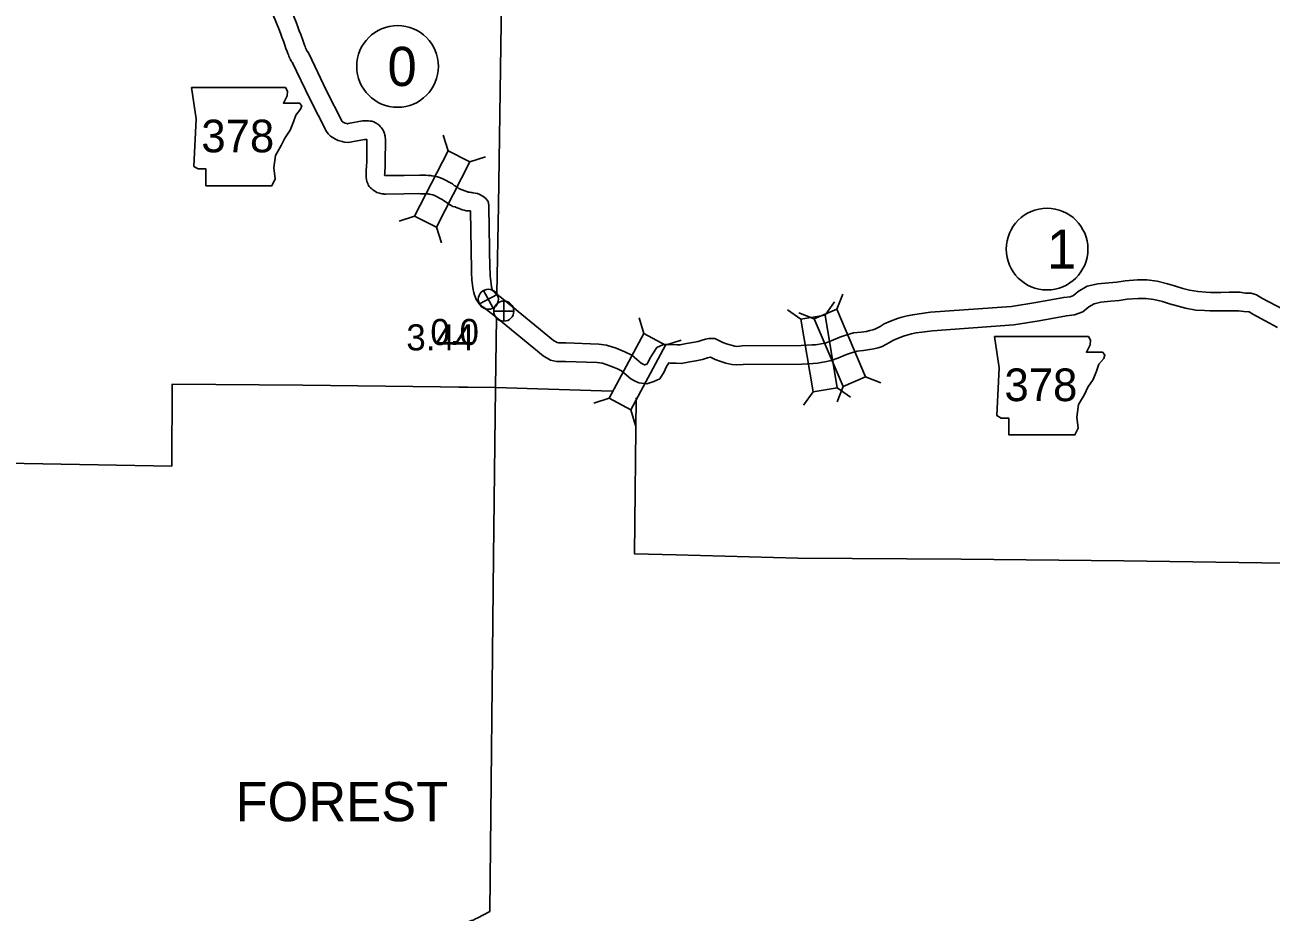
# Model space of a CAD drawing. Extents: x -939622 to -934245, y 1383184 to 1385301.
# Drawn here: x -936377.4 to -936316.9, y 1384357.3 to 1384400.3 of the extents above; entities that cross this region are included whole.
import ezdxf

# ---------------------------------------------------------------- set-up
doc = ezdxf.new("R2010")
doc.units = 0
for name, color, linetype in [('Level 10', 7, 'Continuous'), ('Level 2', 7, 'Continuous'), ('Level 20', 7, 'Continuous'), ('Level 21', 7, 'Continuous'), ('Level 25', 7, 'Continuous'), ('Level 26', 7, 'Continuous'), ('Level 27', 7, 'Continuous'), ('Level 8', 7, 'Continuous')]:
    doc.layers.add(name, color=color, linetype=linetype)

msp = doc.modelspace()

# ---------------------------------------------------------------- linework, layer by layer
at = {"layer": 'Level 10'}
msp.add_line((-936355.168, 1384391.993), (-936355.035, 1384391.879), dxfattribs=at)
for points in [[(-936365.019, 1384402.168), (-936364.906, 1384401.963), (-936364.844, 1384401.842), (-936364.785, 1384401.715), (-936364.684, 1384401.489), (-936364.576, 1384401.252), (-936364.486, 1384401.057), (-936364.413, 1384400.891), (-936364.343, 1384400.709), (-936364.234, 1384400.432), (-936364.146, 1384400.206), (-936364.076, 1384400.007), (-936364.006, 1384399.825), (-936363.927, 1384399.604), (-936363.877, 1384399.456), (-936363.819, 1384399.307), (-936363.799, 1384399.248), (-936363.773, 1384399.191), (-936363.748, 1384399.126), (-936363.728, 1384399.082), (-936363.706, 1384399.033)], [(-936365.806, 1384401.733), (-936365.701, 1384401.542), (-936365.653, 1384401.448), (-936365.603, 1384401.341), (-936365.504, 1384401.119), (-936365.394, 1384400.877), (-936365.307, 1384400.688), (-936365.246, 1384400.549), (-936365.182, 1384400.383), (-936365.072, 1384400.104), (-936364.99, 1384399.892), (-936364.92, 1384399.696), (-936364.85, 1384399.512), (-936364.777, 1384399.308), (-936364.723, 1384399.15), (-936364.665, 1384399), (-936364.636, 1384398.914), (-936364.602, 1384398.84), (-936364.578, 1384398.779), (-936364.549, 1384398.715), (-936364.529, 1384398.668)], [(-936363.716, 1384399.054), (-936363.701, 1384399.024), (-936363.681, 1384398.999), (-936363.617, 1384398.904)], [(-936363.617, 1384398.904), (-936362.759, 1384397.105), (-936362.001, 1384395.604), (-936361.982, 1384395.593), (-936361.91, 1384395.558), (-936361.86, 1384395.531), (-936361.832, 1384395.523), (-936361.776, 1384395.51), (-936361.754, 1384395.504), (-936361.735, 1384395.502), (-936361.709, 1384395.508), (-936361.015, 1384395.638), (-936360.907, 1384395.642), (-936360.845, 1384395.647), (-936360.719, 1384395.643), (-936360.644, 1384395.632), (-936360.558, 1384395.622), (-936360.459, 1384395.59), (-936360.374, 1384395.549), (-936360.319, 1384395.512), (-936360.286, 1384395.487), (-936360.274, 1384395.479), (-936360.187, 1384395.419), (-936360.131, 1384395.345), (-936360.108, 1384395.318), (-936360.092, 1384395.299), (-936360.064, 1384395.262), (-936360.007, 1384395.184), (-936359.98, 1384395.112), (-936359.944, 1384395.035), (-936359.929, 1384394.95), (-936359.918, 1384394.903), (-936359.907, 1384394.831), (-936359.901, 1384394.76), (-936359.9, 1384394.688), (-936359.909, 1384393.675), (-936359.905, 1384393.599), (-936359.911, 1384393.476), (-936359.934, 1384393.111), (-936359.937, 1384393.003), (-936359.928, 1384393), (-936359.89, 1384392.989), (-936359.89, 1384392.989), (-936359.869, 1384392.987), (-936358.992, 1384393)], [(-936364.519, 1384398.647), (-936364.467, 1384398.545), (-936364.414, 1384398.476), (-936364.383, 1384398.429)], [(-936364.416, 1384398.486), (-936363.567, 1384396.709), (-936362.765, 1384395.119), (-936362.685, 1384395.009), (-936362.566, 1384394.892), (-936362.407, 1384394.799), (-936362.322, 1384394.758), (-936362.198, 1384394.69), (-936362.058, 1384394.652), (-936361.994, 1384394.636), (-936361.945, 1384394.624), (-936361.871, 1384394.607), (-936361.697, 1384394.591), (-936361.534, 1384394.625), (-936360.912, 1384394.741), (-936360.852, 1384394.744), (-936360.824, 1384394.746), (-936360.805, 1384394.745), (-936360.803, 1384394.737), (-936360.801, 1384394.725), (-936360.801, 1384394.717), (-936360.8, 1384394.688), (-936360.809, 1384393.654), (-936360.806, 1384393.598), (-936360.81, 1384393.528), (-936360.834, 1384393.149), (-936360.839, 1384392.901), (-936360.824, 1384392.805), (-936360.808, 1384392.697), (-936360.761, 1384392.597), (-936360.735, 1384392.544), (-936360.686, 1384392.465), (-936360.618, 1384392.389), (-936360.567, 1384392.345), (-936360.506, 1384392.295), (-936360.428, 1384392.245), (-936360.309, 1384392.172), (-936360.182, 1384392.137), (-936360.124, 1384392.119), (-936360.063, 1384392.102), (-936359.999, 1384392.095), (-936359.956, 1384392.091), (-936359.888, 1384392.087), (-936359.003, 1384392.1)], [(-936358.992, 1384393), (-936358.223, 1384393.012), (-936358.172, 1384393.004), (-936358.149, 1384393.006), (-936358.036, 1384393.007), (-936358.009, 1384393.004), (-936357.935, 1384393.012), (-936357.851, 1384392.998), (-936357.821, 1384392.996), (-936357.751, 1384392.993), (-936357.699, 1384392.987), (-936357.643, 1384392.984), (-936357.54, 1384392.965), (-936357.472, 1384392.943), (-936357.44, 1384392.938), (-936357.367, 1384392.922), (-936357.322, 1384392.914), (-936357.231, 1384392.887), (-936357.117, 1384392.829), (-936356.645, 1384392.587), (-936356.56, 1384392.514), (-936356.391, 1384392.402), (-936356.344, 1384392.369), (-936356.338, 1384392.365), (-936356.309, 1384392.353), (-936356.183, 1384392.304)], [(-936356.183, 1384392.304), (-936355.921, 1384392.202), (-936355.909, 1384392.197), (-936355.864, 1384392.187), (-936355.824, 1384392.176), (-936355.763, 1384392.172), (-936355.702, 1384392.16), (-936355.655, 1384392.156), (-936355.436, 1384392.127), (-936355.314, 1384392.063), (-936355.304, 1384392.057), (-936355.272, 1384392.046), (-936355.2, 1384392.01), (-936355.168, 1384391.993)], [(-936359.003, 1384392.1), (-936358.287, 1384392.111), (-936358.193, 1384392.096), (-936358.096, 1384392.107), (-936358.084, 1384392.107), (-936358.014, 1384392.099), (-936357.978, 1384392.102), (-936357.861, 1384392.097), (-936357.823, 1384392.096), (-936357.779, 1384392.09), (-936357.755, 1384392.089), (-936357.682, 1384392.065), (-936357.606, 1384392.053), (-936357.554, 1384392.042), (-936357.527, 1384392.028), (-936357.149, 1384391.834), (-936357.102, 1384391.794), (-936356.897, 1384391.657), (-936356.841, 1384391.619), (-936356.763, 1384391.57), (-936356.736, 1384391.558), (-936356.632, 1384391.487), (-936356.535, 1384391.475), (-936356.509, 1384391.465)], [(-936355.035, 1384391.879), (-936354.918, 1384391.731), (-936354.886, 1384391.552), (-936354.886, 1384391.529), (-936354.877, 1384391.473), (-936354.834, 1384388.445), (-936354.826, 1384388.317), (-936354.826, 1384388.231), (-936354.817, 1384388.109), (-936354.808, 1384388.015), (-936354.756, 1384387.595), (-936354.751, 1384387.574), (-936354.739, 1384387.54), (-936354.719, 1384387.463), (-936354.716, 1384387.451), (-936354.708, 1384387.433), (-936354.651, 1384387.358), (-936354.618, 1384387.326), (-936354.591, 1384387.306), (-936354.499, 1384387.235)], [(-936356.499, 1384391.461), (-936356.248, 1384391.363), (-936356.17, 1384391.333), (-936356.082, 1384391.314), (-936355.978, 1384391.285), (-936355.774, 1384391.271)], [(-936355.774, 1384391.271), (-936355.733, 1384388.413), (-936355.726, 1384388.288), (-936355.725, 1384388.194), (-936355.714, 1384388.034), (-936355.703, 1384387.918), (-936355.644, 1384387.444), (-936355.618, 1384387.322), (-936355.599, 1384387.272), (-936355.588, 1384387.23), (-936355.567, 1384387.152), (-936355.531, 1384387.068), (-936355.496, 1384386.985), (-936355.449, 1384386.911), (-936355.353, 1384386.765), (-936355.237, 1384386.672), (-936355.203, 1384386.639), (-936355.133, 1384386.588), (-936354.526, 1384386.119)], [(-936354.181, 1384386.989), (-936351.747, 1384384.988), (-936351.57, 1384384.89), (-936351.507, 1384384.876), (-936351.142, 1384384.874), (-936349.55, 1384384.818), (-936349.169, 1384384.764), (-936348.711, 1384384.612), (-936348.476, 1384384.517), (-936348.293, 1384384.447), (-936347.954, 1384384.283), (-936347.727, 1384384.085), (-936347.491, 1384383.887), (-936347.364, 1384383.819), (-936347.336, 1384383.804), (-936347.312, 1384383.801), (-936347.219, 1384383.833), (-936347.213, 1384383.835), (-936347.17, 1384383.902), (-936347.072, 1384384.11), (-936346.916, 1384384.379), (-936346.731, 1384384.648), (-936346.412, 1384384.792), (-936346.17, 1384384.799), (-936346.062, 1384384.796), (-936345.746, 1384384.781), (-936345.615, 1384384.774), (-936345.298, 1384384.836), (-936345.007, 1384384.886), (-936344.733, 1384384.944), (-936344.529, 1384385.003), (-936344.369, 1384385.052), (-936344.21, 1384385.084), (-936343.919, 1384385.086), (-936343.541, 1384384.892), (-936343.353, 1384384.824), (-936343.136, 1384384.757), (-936342.954, 1384384.71), (-936342.854, 1384384.704), (-936342.59, 1384384.723), (-936339.73, 1384384.743), (-936339.208, 1384384.777), (-936339.036, 1384384.786), (-936338.675, 1384384.847), (-936338.53, 1384384.879), (-936338.28, 1384384.967), (-936337.863, 1384385.146), (-936337.563, 1384385.247), (-936337.202, 1384385.354), (-936336.826, 1384385.394), (-936336.572, 1384385.432), (-936336.401, 1384385.466), (-936336.257, 1384385.5), (-936336.167, 1384385.531), (-936335.907, 1384385.667), (-936335.713, 1384385.795), (-936335.394, 1384385.923), (-936335.067, 1384386.05), (-936334.856, 1384386.115), (-936334.592, 1384386.186), (-936334.322, 1384386.242), (-936334.015, 1384386.289), (-936333.461, 1384386.359), (-936329.53, 1384386.643), (-936328.351, 1384386.836), (-936326.998, 1384387.082), (-936326.687, 1384387.114), (-936326.521, 1384387.176), (-936326.293, 1384387.361), (-936325.856, 1384387.617), (-936325.344, 1384387.736), (-936324.807, 1384387.785), (-936324.421, 1384387.826), (-936324.025, 1384387.889), (-936323.418, 1384387.926), (-936322.968, 1384387.927), (-936322.475, 1384387.864), (-936321.972, 1384387.745), (-936321.619, 1384387.637), (-936321.215, 1384387.519), (-936320.893, 1384387.433), (-936320.486, 1384387.36), (-936320.115, 1384387.336), (-936319.884, 1384387.321), (-936319.379, 1384387.325), (-936318.97, 1384387.329), (-936318.455, 1384387.331), (-936318.187, 1384387.287), (-936317.904, 1384387.279), (-936317.647, 1384387.207), (-936317.385, 1384387.048), (-936316.346, 1384386.492)], [(-936354.517, 1384386.1), (-936352.255, 1384384.241), (-936351.89, 1384384.038), (-936351.605, 1384383.977), (-936351.161, 1384383.974), (-936349.63, 1384383.92), (-936349.375, 1384383.884), (-936349.021, 1384383.767), (-936348.805, 1384383.68), (-936348.651, 1384383.621), (-936348.455, 1384383.525), (-936348.313, 1384383.402), (-936347.999, 1384383.137), (-936347.783, 1384383.022), (-936347.606, 1384382.93), (-936347.217, 1384382.883), (-936346.874, 1384382.999), (-936346.593, 1384383.137), (-936346.382, 1384383.463), (-936346.275, 1384383.69), (-936346.154, 1384383.898), (-936346.154, 1384383.898), (-936346.095, 1384383.897), (-936345.793, 1384383.882), (-936345.552, 1384383.869), (-936345.134, 1384383.951), (-936344.838, 1384384.002), (-936344.515, 1384384.07), (-936344.271, 1384384.141), (-936344.149, 1384384.178), (-936344.129, 1384384.182), (-936343.902, 1384384.066), (-936343.639, 1384383.97), (-936343.382, 1384383.891), (-936343.095, 1384383.817), (-936342.848, 1384383.802), (-936342.554, 1384383.823), (-936339.698, 1384383.843), (-936339.154, 1384383.879), (-936338.937, 1384383.891), (-936338.503, 1384383.963), (-936338.282, 1384384.012), (-936337.953, 1384384.128), (-936337.541, 1384384.305), (-936337.291, 1384384.389), (-936337.025, 1384384.468), (-936336.712, 1384384.501), (-936336.416, 1384384.545), (-936336.21, 1384384.587), (-936336.007, 1384384.634), (-936335.811, 1384384.702), (-936335.45, 1384384.89), (-936335.293, 1384384.993), (-936335.064, 1384385.086), (-936334.77, 1384385.199), (-936334.604, 1384385.251), (-936334.384, 1384385.31), (-936334.163, 1384385.356), (-936333.89, 1384385.398), (-936333.372, 1384385.463), (-936329.424, 1384385.749), (-936328.198, 1384385.95), (-936326.871, 1384386.19), (-936326.481, 1384386.231), (-936326.069, 1384386.384), (-936325.779, 1384386.619), (-936325.519, 1384386.771), (-936325.2, 1384386.846), (-936324.719, 1384386.89), (-936324.303, 1384386.934), (-936323.927, 1384386.993), (-936323.39, 1384387.026), (-936323.025, 1384387.027), (-936322.636, 1384386.977), (-936322.208, 1384386.876), (-936321.876, 1384386.774), (-936321.457, 1384386.653), (-936321.089, 1384386.553), (-936320.595, 1384386.466), (-936320.174, 1384386.438), (-936319.908, 1384386.421), (-936319.371, 1384386.426), (-936318.965, 1384386.429), (-936318.527, 1384386.43), (-936318.272, 1384386.389), (-936318.04, 1384386.383), (-936318.009, 1384386.374), (-936317.831, 1384386.266), (-936316.63, 1384385.623)], [(-936354.488, 1384387.227), (-936354.192, 1384386.997)]]:
    msp.add_lwpolyline(points, dxfattribs=at)
at = {"layer": 'Level 2'}
for points in [[(-936354.499, 1384387.27), (-936354.41, 1384391.534), (-936354.205, 1384405.921), (-936357.731, 1384405.958), (-936357.73, 1384406.03)], [(-936354.499, 1384387.266), (-936354.41, 1384391.534), (-936354.205, 1384405.921), (-936357.731, 1384405.958), (-936357.73, 1384406.03)], [(-936354.653, 1384374.501), (-936354.565, 1384382.691), (-936354.518, 1384386.112)], [(-936354.653, 1384374.501), (-936354.565, 1384382.691), (-936354.519, 1384386.084)], [(-936356.348, 1384356.69), (-936356.268, 1384356.71), (-936356.19, 1384356.718), (-936356.125, 1384356.737), (-936356.023, 1384356.748), (-936355.943, 1384356.771), (-936355.836, 1384356.812), (-936355.72, 1384356.85), (-936355.646, 1384356.873), (-936355.527, 1384356.939), (-936355.423, 1384356.98), (-936354.837, 1384357.286), (-936354.653, 1384374.501)], [(-936356.348, 1384356.69), (-936356.268, 1384356.71), (-936356.19, 1384356.718), (-936356.125, 1384356.737), (-936356.023, 1384356.748), (-936355.943, 1384356.771), (-936355.836, 1384356.812), (-936355.72, 1384356.85), (-936355.646, 1384356.873), (-936355.527, 1384356.939), (-936355.423, 1384356.98), (-936354.837, 1384357.286), (-936354.653, 1384374.501)]]:
    msp.add_lwpolyline(points, dxfattribs=at)
at = {"layer": 'Level 20'}
for p, q in [((-936356.856, 1384394.193), (-936357.098, 1384394.947)), ((-936355.799, 1384393.65), (-936355.045, 1384393.892)), ((-936358.485, 1384391.023), (-936359.24, 1384390.781)), ((-936357.429, 1384390.48), (-936357.187, 1384389.726)), ((-936338.577, 1384386.214), (-936338.117, 1384386.859)), ((-936338.013, 1384386.501), (-936337.719, 1384387.237)), ((-936347.364, 1384385.328), (-936347.595, 1384386.086)), ((-936339.749, 1384386.018), (-936340.394, 1384386.477)), ((-936339.105, 1384386.033), (-936339.84, 1384386.327)), ((-936346.316, 1384384.769), (-936345.558, 1384385)), ((-936336.608, 1384383.226), (-936335.872, 1384382.932)), ((-936339.16, 1384382.503), (-936339.62, 1384381.858)), ((-936337.7, 1384382.758), (-936337.993, 1384382.022)), ((-936337.988, 1384382.699), (-936337.343, 1384382.239)), ((-936349.041, 1384382.184), (-936349.799, 1384381.953)), ((-936347.993, 1384381.624), (-936347.763, 1384380.867))]:
    msp.add_line(p, q, dxfattribs=at)
for points in [[(-936356.856, 1384394.193), (-936358.485, 1384391.023), (-936357.429, 1384390.48), (-936355.799, 1384393.65)], [(-936337.988, 1384382.699), (-936338.577, 1384386.214), (-936339.749, 1384386.018), (-936339.16, 1384382.503)], [(-936336.608, 1384383.226), (-936338.013, 1384386.501), (-936339.105, 1384386.033), (-936337.7, 1384382.758)], [(-936347.993, 1384381.624), (-936346.316, 1384384.769), (-936347.364, 1384385.328), (-936349.041, 1384382.184)]]:
    msp.add_lwpolyline(points, close=True, dxfattribs=at)
at = {"layer": 'Level 21'}
for points in [[(-936369.314, 1384397.268), (-936369.086, 1384395.745), (-936369.188, 1384393.436), (-936368.985, 1384393.309), (-936368.604, 1384393.309), (-936368.604, 1384392.497), (-936365.406, 1384392.497), (-936365.254, 1384392.827), (-936365.305, 1384393.36), (-936365.229, 1384393.969), (-936364.95, 1384394.451), (-936364.772, 1384394.806), (-936364.518, 1384395.187), (-936364.366, 1384395.593), (-936364.239, 1384395.923), (-936364.011, 1384396.202), (-936363.96, 1384396.379), (-936364.061, 1384396.506), (-936364.848, 1384396.506), (-936364.67, 1384396.862), (-936364.645, 1384397.09), (-936364.75, 1384397.265)], [(-936330.365, 1384385.18), (-936330.137, 1384383.657), (-936330.238, 1384381.348), (-936330.035, 1384381.221), (-936329.655, 1384381.221), (-936329.655, 1384380.409), (-936326.457, 1384380.409), (-936326.305, 1384380.739), (-936326.356, 1384381.272), (-936326.28, 1384381.881), (-936326, 1384382.363), (-936325.823, 1384382.718), (-936325.569, 1384383.099), (-936325.417, 1384383.505), (-936325.29, 1384383.835), (-936325.061, 1384384.114), (-936325.011, 1384384.292), (-936325.112, 1384384.418), (-936325.899, 1384384.418), (-936325.721, 1384384.774), (-936325.696, 1384385.002), (-936325.801, 1384385.178)]]:
    msp.add_lwpolyline(points, close=True, dxfattribs=at)
at = {"layer": 'Level 26'}
for p, q in [((-936355.136, 1384387.419), (-936354.679, 1384386.558)), ((-936354.477, 1384387.217), (-936355.338, 1384386.76)), ((-936354.16, 1384385.928), (-936354.16, 1384386.903)), ((-936354.647, 1384386.415), (-936353.672, 1384386.415))]:
    msp.add_line(p, q, dxfattribs=at)
for centre in [(-936354.907, 1384386.989), (-936354.16, 1384386.415)]:
    msp.add_circle(centre, 0.487, dxfattribs=at)
at = {"layer": 'Level 27'}
msp.add_circle((-936327.807, 1384389.42), 1.98, dxfattribs=at)
msp.add_ellipse((-936359.312, 1384398.282), major_axis=(0, 1.98), ratio=0.999998, dxfattribs=at)
at = {"layer": 'Level 8'}
for points in [[(-936402.323, 1384375.401), (-936390.935, 1384375.267), (-936386.299, 1384375.202), (-936378.331, 1384375.112), (-936378.308, 1384379.047), (-936370.264, 1384378.895), (-936370.247, 1384382.866), (-936363.902, 1384382.818)], [(-936363.902, 1384382.818), (-936354.568, 1384382.706)], [(-936356.335, 1384382.727), (-936354.568, 1384382.706)], [(-936354.568, 1384382.706), (-936348.897, 1384382.535)], [(-936347.733, 1384382.204), (-936347.814, 1384374.634), (-936345.794, 1384374.592)], [(-936308.422, 1384374.063), (-936316.278, 1384374.183), (-936324.085, 1384374.302), (-936331.971, 1384374.381), (-936339.891, 1384374.424), (-936345.794, 1384374.592)]]:
    msp.add_lwpolyline(points, dxfattribs=at)

# ---------------------------------------------------------------- texts
at = {"layer": 'Level 21'}
for p in [(-936368.829, 1384394.116), (-936329.874, 1384382.048)]:
    msp.add_text('378', height=1.584, dxfattribs=at).set_placement(p)
at = {"layer": 'Level 25'}
for s, p in [('3.44', (-936358.887, 1384384.508)), ('0.0', (-936357.72, 1384384.767))]:
    msp.add_text(s, height=1.2672, dxfattribs=at).set_placement(p)
at = {"layer": 'Level 27'}
for s, p in [('0', (-936359.796, 1384397.332)), ('1', (-936327.807, 1384388.47))]:
    msp.add_text(s, height=1.901, dxfattribs=at).set_placement(p)
at = {"layer": 'Level 8'}
msp.add_text('FOREST', height=1.9008, dxfattribs=at).set_placement((-936367.169, 1384361.673))

doc.saveas('drawing.dxf')
